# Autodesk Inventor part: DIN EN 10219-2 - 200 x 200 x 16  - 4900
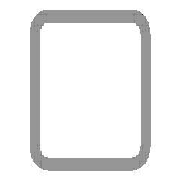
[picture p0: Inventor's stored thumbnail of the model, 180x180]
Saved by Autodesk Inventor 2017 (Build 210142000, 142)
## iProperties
IsCustomPart: 1
Created: 2017-11
Part Number: DIN EN 10219-2 - 200 x 200 x 16  - 4900
Material: Steel, Mild
Description: Cold formed welded structural hollow sections of non-alloy and fine grain structural steel
Document SubType Name: Modeling
Standard: DIN
Designer: iusti
Standard Revision: 2006-07
Standards Organization: DIN
Language: en-US
Size Designation: 200 x 200 x 16
Categories: <MemberInstance><Categories><Category DisplayName="Structural Shapes" InternalName="089c4875-fa83-4c05-b084-43b9cc11f5ed" Mnemonic="GRDR"><CategoryParameter Dis
Stock Number: 200 x 200 x 16
Density: 7.85 g/cm^3
Appearance: Semi-Polished
Mass: 410700 g
Surface Area: 65611.6 cm^2
Volume: 52318.5 cm^3
_CCFamilyMember: 103
_CCFamilyDisplayName: DIN EN 10219-2 (Square Hollow Section - Cold Formed) - Cold formed welded structural hollow sections of non-alloy and fine grain structural steel
_FrameMemberDoc: Frame Member File
_Version: 15.0.0
_GetPNFromCC: 1
G_L: 4900.000 mm
G_W: 200.000 mm
G_H: 200.000 mm
+64C0199E-E4A6-42EE-BAB6-C57CBAF8A212+CUTDETAIL1: Cut
Author: iusti
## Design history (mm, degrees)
node "Start plane"
node "End plane"
sketch "Sketch"
  geometry: L1 (-100, -52)-(-100, 52); L2 (-52, 100)-(52, 100); L3 (100, 52)-(100, -52); L4 (52, -100)-(-52, -100); L5 (-52, 84)-(52, 84); L6 (84, 52)-(84, -52); L7 (52, -84)-(-52, -84); L8 (-84, -52)-(-84, 52); L9 (0, 293.918)-(0, -293.918) reference; L10 (-293.918, 0)-(293.918, 0) reference; A1 r 48 centre (-52, -52) between (-100, -52) and (-52, -100); A2 r 48 centre (-52, 52) between (-52, 100) and (-100, 52); A3 r 48 centre (52, 52) between (100, 52) and (52, 100); A4 r 48 centre (52, -52) between (52, -100) and (100, -52); A5 r 32 centre (-52, 52) between (-52, 84) and (-84, 52); A6 r 32 centre (52, 52) between (84, 52) and (52, 84); A7 r 32 centre (52, -52) between (52, -84) and (84, -52); A8 r 32 centre (-52, -52) between (-84, -52) and (-52, -84)
  constraints: 16 end point, 16 point on circle, 8 centre point, 8 tangent, 4 parallel, 3 equal radius, 2 perpendicular, 7 other
  dimensions: "d7" = 48 radius of A1 (= G_IR); "d10" = 200 distance between parallel lines of L2 L4 (= G_H); "d11" = 200 distance between parallel lines of L1 L3 (= G_W); "d12" = 16 distance between parallel lines of L3 L6 (= G_T); "d15" = 100 distance between parallel lines of L2 L10 (= 0.5 x d10); "d16" = 100 distance between parallel lines of L9 L3 (= 0.5 x d11)
extrude "Body" new body sketch "Sketch" stored distance "d3" = 4900 (= G_L); taper "d4" = 0 deg
node "Driven Length"
  sketch "Sketch3"
    geometry: L1 (0, 0)-(10, 0) reference
    constraints: 2 end point, 1 horizontal
  workplane "Work Plane3"
  sketch "Sketch4"
    geometry: L1 (-2, 0)-(12, 0) reference; L2 (-2, 4900)-(12, 4900) reference
    dimensions: "d18" = 4900 distance between parallel lines of L1 L2 (derived)
workplane "Work Plane4"
split "Split1"
body "Solid1"
other parameters: "G_W" = 200 [user parameter; used in 1 equation term], "G_H" = 200 [user parameter; used in 1 equation term], "G_T" = 16 [user parameter; used in 1 equation term], "G_IR" = 48 [user parameter; used in 1 equation term], "G_L" = 4900 (= d18) [user parameter; used in 1 equation term], "G_OFFSET_START" = 0 [user parameter; used in 1 equation term], "d13" = 0 (computed from G_OFFSET_START), "d17" = 90 deg
